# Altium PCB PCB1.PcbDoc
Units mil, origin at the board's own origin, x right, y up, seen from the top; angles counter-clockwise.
Board outline 5000 x 4000 mil, 2 copper layers (Top Layer, Bottom Layer); 2 components, 2 nets, 16 pads, 0 vias.
Unrouted connection lines stored in the file: 2.
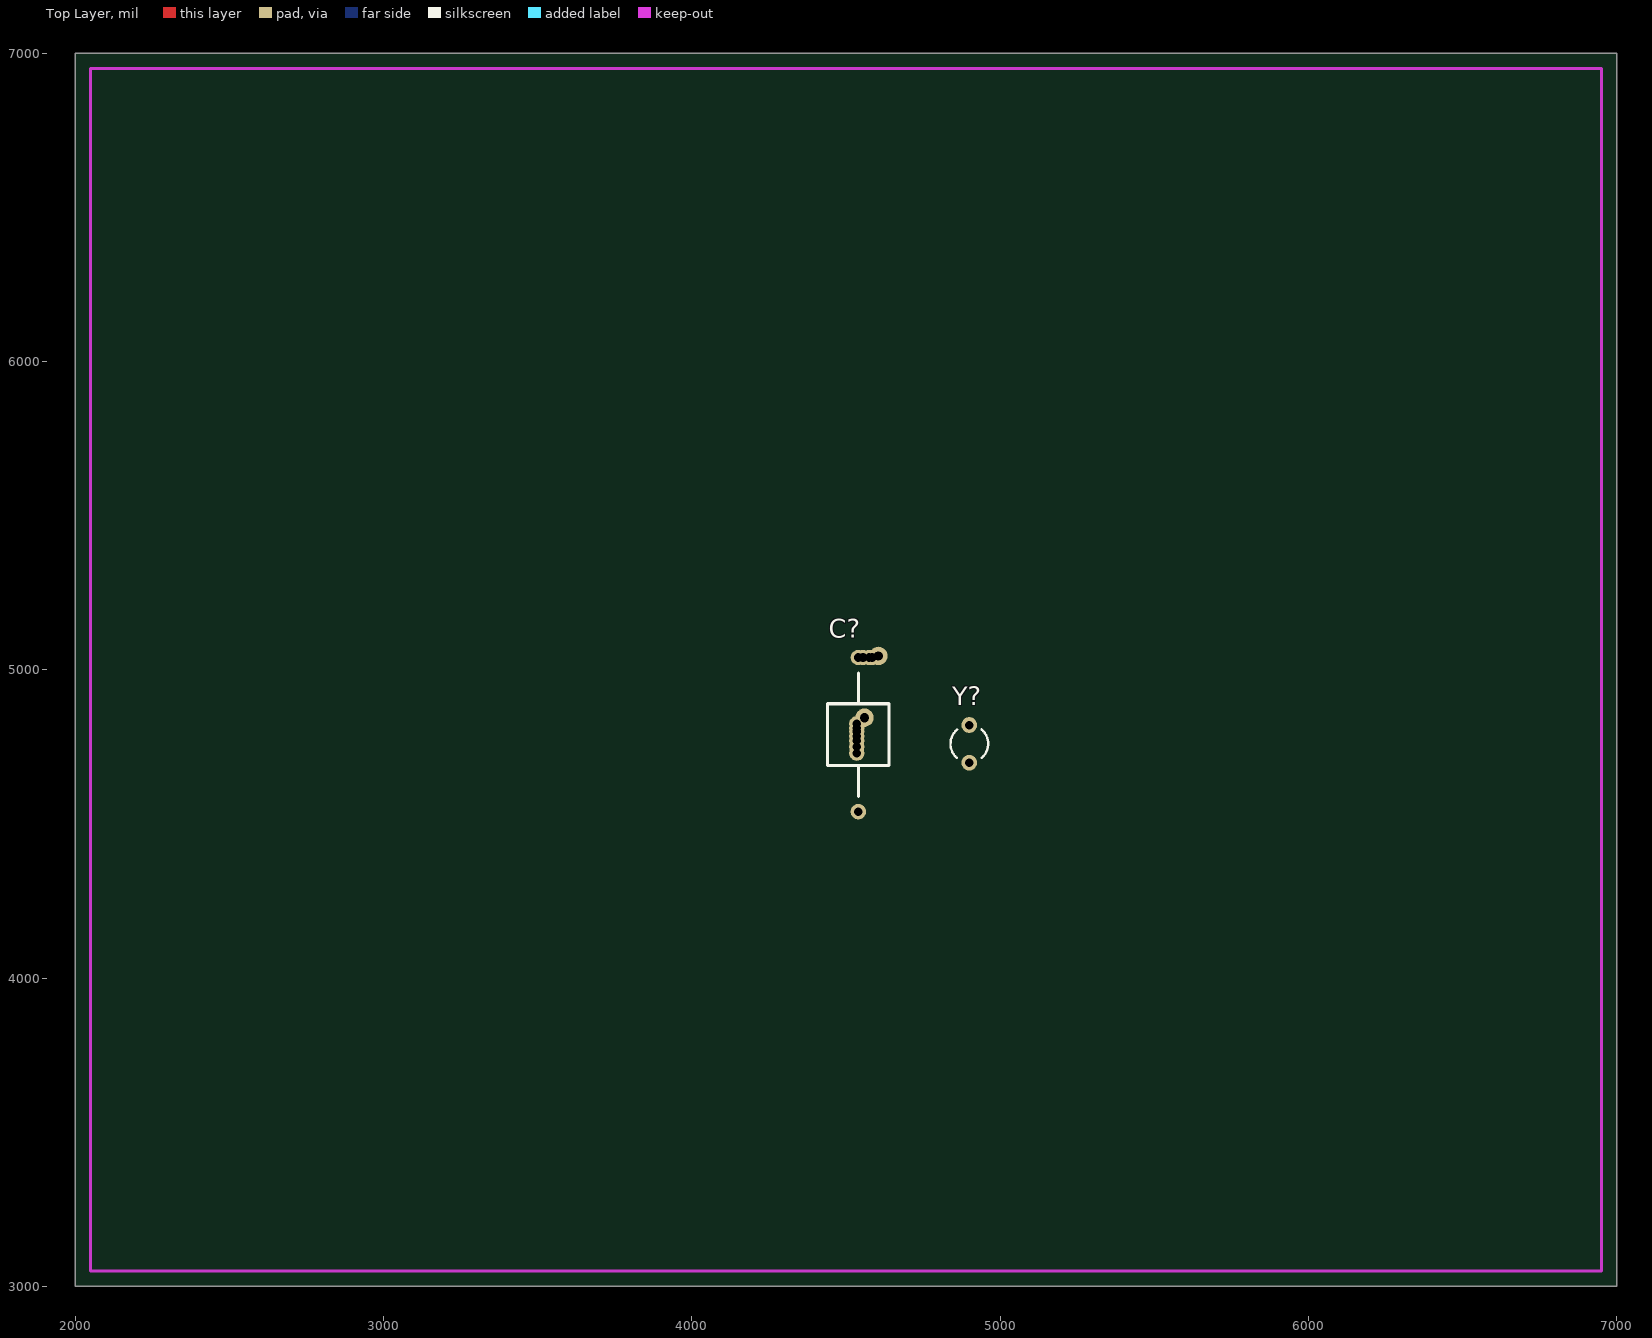
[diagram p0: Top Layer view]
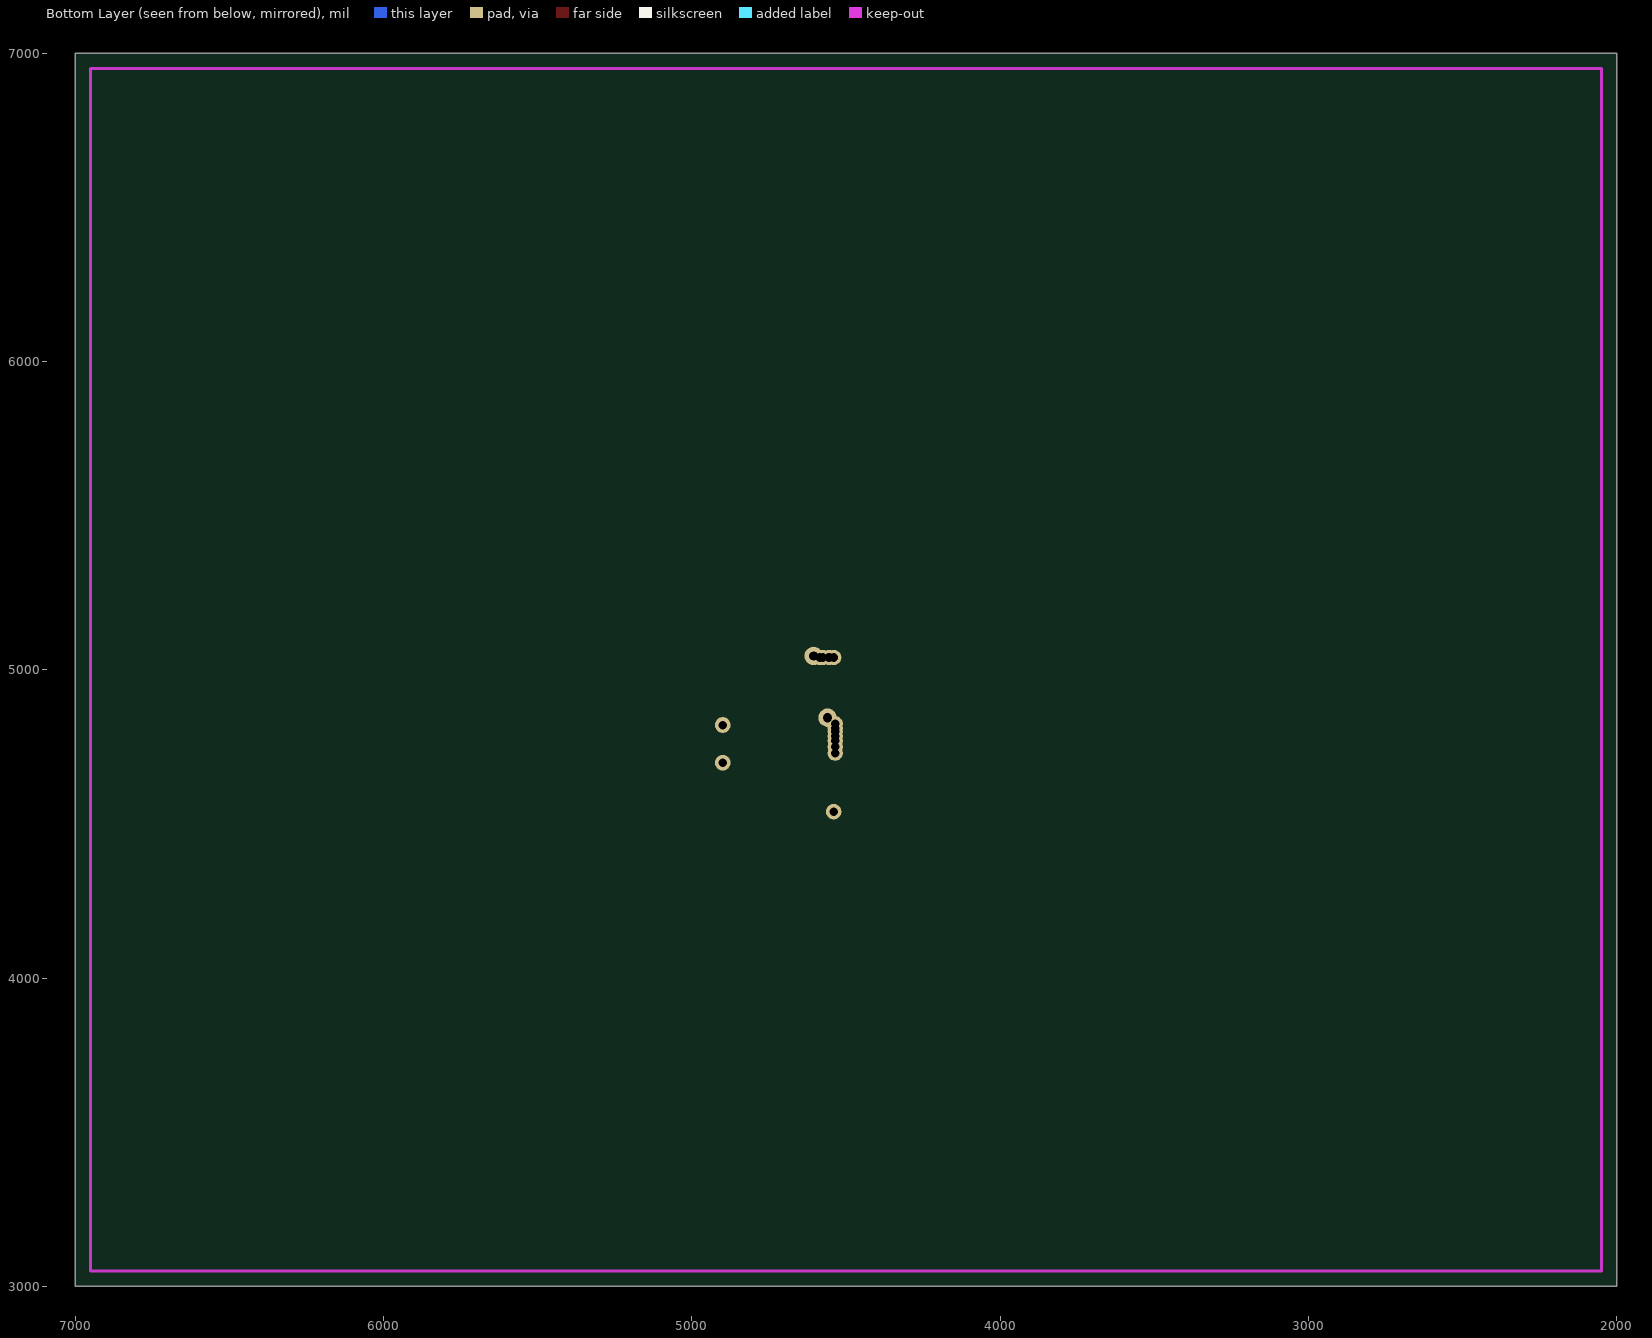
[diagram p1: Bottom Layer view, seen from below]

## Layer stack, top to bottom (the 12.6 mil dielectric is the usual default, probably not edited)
Top Layer: signal copper 1.4
Dielectric: dielectric 12.6, FR-4, Dk 4.8
Bottom Layer: signal copper 1.4

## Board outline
2000,3000 7000,3000 7000,7000 2000,7000

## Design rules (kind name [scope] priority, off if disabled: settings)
Clearance [All] p1: gap=8
ComponentClearance [All] p1: gap=10 collisioncheckmode=3 verticalgap=10
PolygonConnect [All] p1: connectstyle=Relief reliefconductorwidth=10 reliefentries=4 polygonreliefangle="90 Angle"
RoutingVias [All] p1: holewidth=25 width=40 viastyle="Through Hole" minholewidth=28 minwidth=50 maxholewidth=28 maxwidth=50
SolderMaskExpansion [All] p1: expansion=4
TestPointUsage [All] p1: valid=0 allowmultiple=FALSE
Testpoint [All] p1: side=15 testpointundercomponent=TRUE minsize=40 maxsize=100 preferedsize=60 minholesize=0 maxholesize=40 preferedholesize=32 testpointgrid=1 style=1023 order=0123456789
Width [All] p1: maxlimit=8 minlimit=8 preferedwidth=8
17 further rules are at their usual default settings.

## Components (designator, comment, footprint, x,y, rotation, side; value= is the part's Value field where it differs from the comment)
C? "Cap" Capacitor 4540,4540 r90 top
Y? "XTAL" BCY-W2/D3.1 4900,4760 r180 top

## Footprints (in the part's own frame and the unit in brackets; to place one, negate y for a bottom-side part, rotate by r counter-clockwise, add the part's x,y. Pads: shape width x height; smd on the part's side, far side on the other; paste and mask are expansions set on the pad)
BCY-W2/D3.1 [mm] "Crystal, Thru-Hole; 2 Leads; Body 3.1 x 8.2 mm (Dia.xH)"
  round 1.3 hole 0.7: 1(0,1.55) 2(0,-1.55)
  silkscreen extent -1.55,-1.19 1.55,1.17
Capacitor [mil]
  round 50 hole 28: 0(190,5) 0(210,5) 0(230,5) 0(245,5) 0(260,5) 0(270,5) 0(285,5) 1(0,0) 2(500,-45) 2(500,-35) 2(500,-15) 2(500,0)
  silkscreen extent 50,-100 450,100

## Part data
C?: "Capacitor"
Y?: "Crystal Oscillator"

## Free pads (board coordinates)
  round 60 hole 30: 0(4605,5045) 1(4560,4845)

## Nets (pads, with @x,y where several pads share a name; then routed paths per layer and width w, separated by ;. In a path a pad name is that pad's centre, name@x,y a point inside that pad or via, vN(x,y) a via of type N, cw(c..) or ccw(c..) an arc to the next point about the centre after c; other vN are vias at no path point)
NetC?_1: C?.1 Y?.1
NetC?_2: C?.2 pad.0 Y?.2
pads on no net: C?.0

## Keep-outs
Keep-Out Layer:
  lines w10: 2050,3050 2050,6950 6950,6950 6950,3050 2050,3050

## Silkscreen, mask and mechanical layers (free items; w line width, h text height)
Drill Drawing:
  text ".LEGEND" at 7200,3200 h60
  text "Drill Drawing." at 7200,3100 h60

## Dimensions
2050,3050 to 2050,6950 on Mechanical 1
2050,3050 to 6950,3050 on Mechanical 1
